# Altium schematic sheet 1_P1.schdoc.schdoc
size 309 x 223 mm; Symbol: Sheet-Symbol_A4; Device: Sheet-Symbol_A4; @Project Name: stm32wb5mmg01; @Page Count: 1; @Update Date: 2024-01-22; @Create Date: 2024-01-22; @Schematic Name: Schematic1; @Page No: 1; @Page Name: P1; Company: EasyEDA.com; Reviewed: EasyEDA; Version: V0.1; Page Size: A4; Part Number: JLCPCB-002; Drawn: EasyEDA
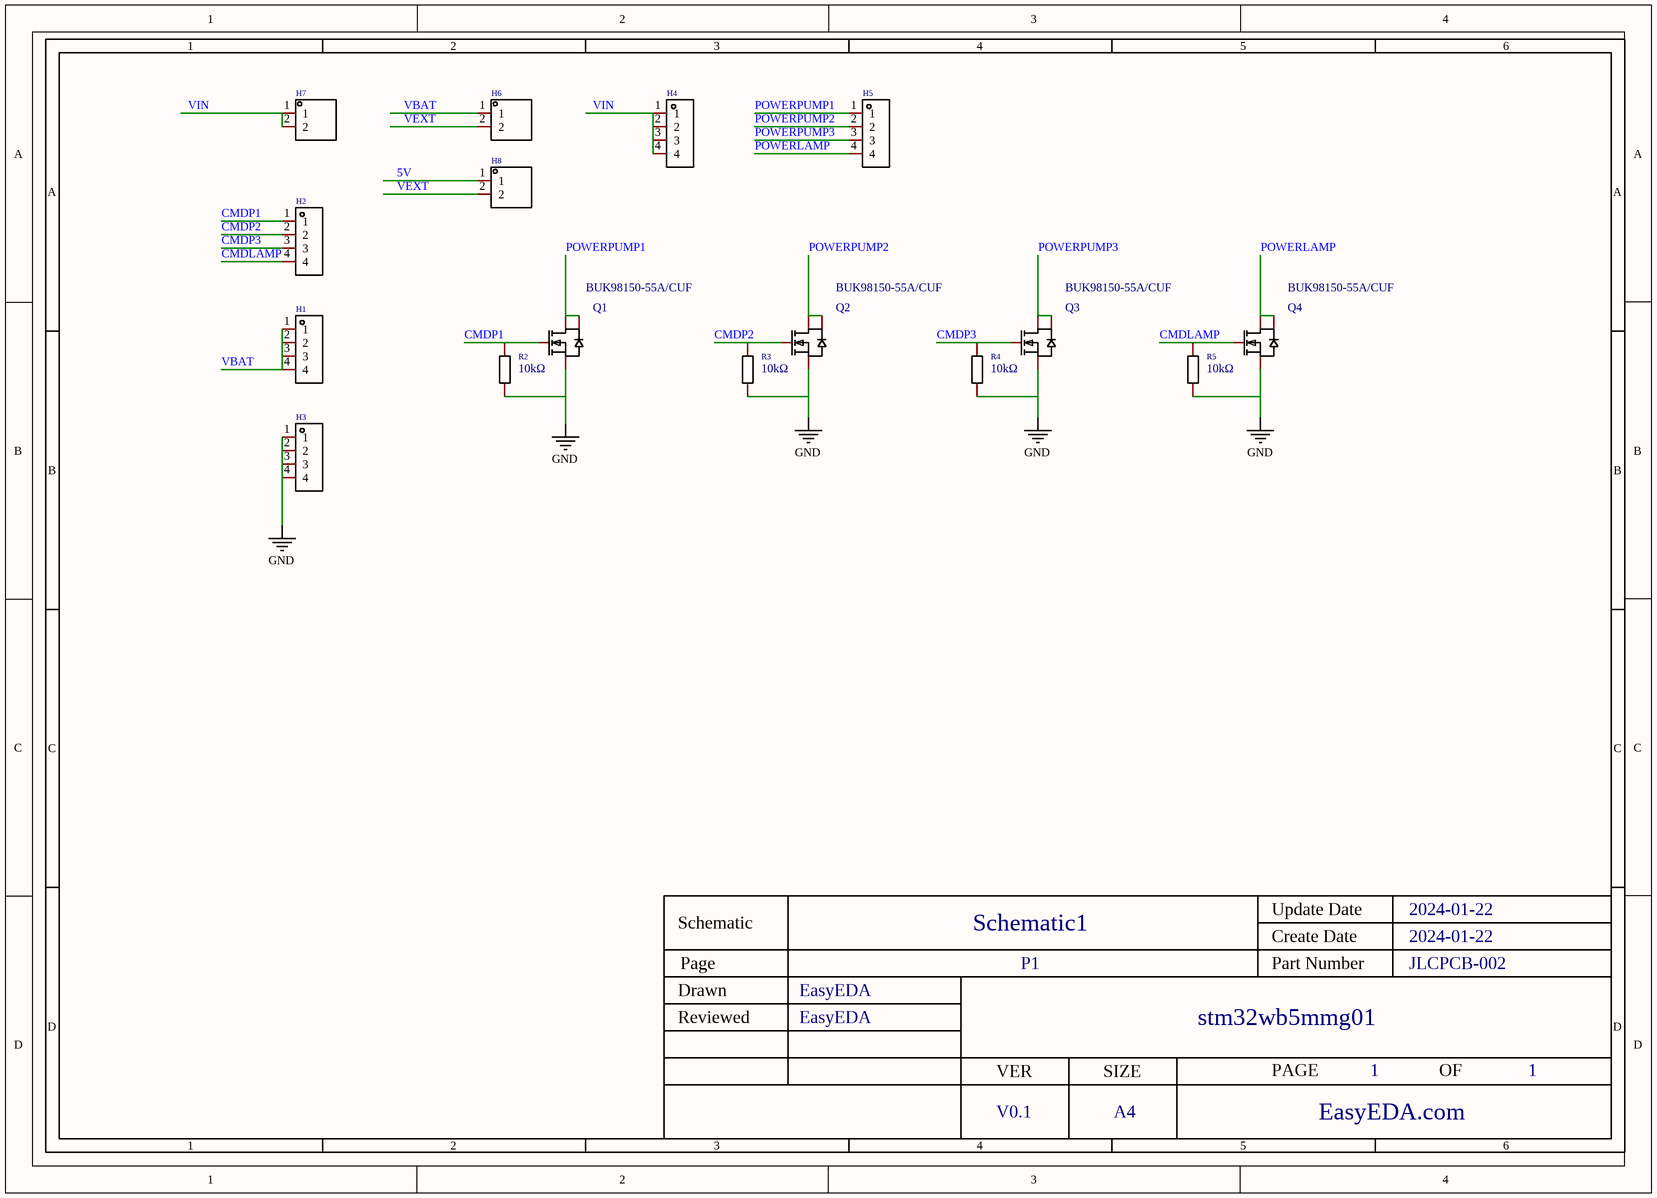
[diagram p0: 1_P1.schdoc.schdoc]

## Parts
H1  HDR-M_2.54_1x4P  [HDR-TH_4P-P2.54-V-M]  (value not drawn)
H2  HDR-M_2.54_1x4P  [HDR-TH_4P-P2.54-V-M]  (value not drawn)
H3  HDR-M_2.54_1x4P  [HDR-TH_4P-P2.54-V-M]  (value not drawn)
H4  HDR-M_2.54_1x4P  [HDR-TH_4P-P2.54-V-M]  (value not drawn)
H5  HDR-M_2.54_1x4P  [HDR-TH_4P-P2.54-V-M]  (value not drawn)
H6  HDR-M_2.54_1x2P  [HDR-TH_2P-P2.54-V-M-1]  (value not drawn)
H7  HDR-M_2.54_1x2P  [HDR-TH_2P-P2.54-V-M-1]  (value not drawn)
H8  HDR-M_2.54_1x2P  [HDR-TH_2P-P2.54-V-M-1]  (value not drawn)
Q1  BUK98150-55A/CUF  [SOT-223-3_L6.5-W3.4-P2.30-LS7.0-BR]
Q2  BUK98150-55A/CUF  [SOT-223-3_L6.5-W3.4-P2.30-LS7.0-BR]
Q3  BUK98150-55A/CUF  [SOT-223-3_L6.5-W3.4-P2.30-LS7.0-BR]
Q4  BUK98150-55A/CUF  [SOT-223-3_L6.5-W3.4-P2.30-LS7.0-BR]
R2  10kΩ  [R1206]
R3  10kΩ  [R1206]
R4  10kΩ  [R1206]
R5  10kΩ  [R1206]

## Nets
GND: H3.1 H3.2 H3.3 H3.4 Q1.3(S) Q2.3(S) Q3.3(S) Q4.3(S) R2.1 R3.1 R4.1 R5.1
5V: H8.1
CMDLAMP: H2.4 Q4.1(G) R5.2
CMDP1: H2.1 Q1.1(G) R2.2
CMDP2: H2.2 Q2.1(G) R3.2
CMDP3: H2.3 Q3.1(G) R4.2
POWERLAMP: H5.4 Q4.2(D) Q4.4(D)
POWERPUMP1: H5.1 Q1.2(D) Q1.4(D)
POWERPUMP2: H5.2 Q2.2(D) Q2.4(D)
POWERPUMP3: H5.3 Q3.2(D) Q3.4(D)
VBAT: H1.1 H1.2 H1.3 H1.4 H6.1
VEXT: H6.2 H8.2
VIN: H4.1 H4.2 H4.3 H4.4 H7.1 H7.2

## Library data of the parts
H1-H5 = HDR-M_2.54_1x4P: Manufacturer: XFCN(兴飞); Symbol: PZ254V-11-04P; Convert to PCB: yes
H6-H8 = HDR-M_2.54_1x2P: Manufacturer: Ckmtw(灿科盟); Manufacturer Part: B-2100S02P-A110; Symbol: 210S-1*2P L=11.6MMGold-plated black; Convert to PCB: yes
Q1-Q4 = BUK98150-55A/CUF: Manufacturer: Nexperia(安世); Add into BOM: yes; Drain Source On Resistance (RDS(on)@Vgs,Id): 137mΩ@10V,5A; Gate Threshold Voltage (Vgs(th)@Id): 2V@1mA; Total Gate Charge (Qg@Vgs): 5.3nC@5V; Input Capacitance (Ciss@Vds): 320pF@25V; Description: Type: Drain Source Voltage (Vdss): Continuous Drain Current (Id): Power Dissipation (Pd): Drain Source On Resistance (RDS(on)@Vgs,Id):137mΩ@10V,5A Gate Threshold Voltage (Vgs(th)@Id):2V@1mA Total Gate Charge (Qg@Vgs):5.3nC@5V Input Capacitance (Ciss@Vds):
R2-R5 = 1206W4F1002T5E: Manufacturer: UNI-ROYAL(厚声); Add into BOM: yes; Tolerance: ±1%; Temperature Coefficient: ±100ppm/℃; Description: Resistance:10000Ω Tolerance:±1% Tolerance:±1% Power(Watts): Overload Voltage (Max): Temperature Coefficient:±100ppm/℃ Temperature Coefficient:±100ppm/℃ Type:Thick Film Resistors Operating Temperature Range:-55℃~+155℃ Operating Temperature Range:-55℃~+155℃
